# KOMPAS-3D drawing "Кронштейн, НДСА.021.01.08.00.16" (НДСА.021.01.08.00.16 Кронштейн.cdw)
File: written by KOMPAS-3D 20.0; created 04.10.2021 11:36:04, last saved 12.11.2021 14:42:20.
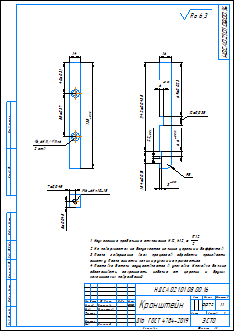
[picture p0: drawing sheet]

Sheet 1: A3, portrait

Document properties: Автор: adminzsc; Параметр неуказанной шероховатости: Ra 6,3; PLM_CDWXDTO: <item xmlns="http://appius.ru/pdm" xmlns:xs="http://www.w3.org/2001/XMLSchema" xmlns:xsi="http://www.w3.org/2001/XMLSchema-instance" xsi:type="item">  <element xmlns:d2p1="http://v8.1c.ru/8.1/data/enterprise/current-config" xsi:type="d2p1:CatalogRef.aps_Элемен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; PDM_DOCXDTO: <item xmlns="http://appius.ru/pdm" xmlns:xs="http://www.w3.org/2001/XMLSchema" xmlns:xsi="http://www.w3.org/2001/XMLSchema-instance" xsi:type="item">  <element xmlns:d2p1="http://v8.1c.ru/8.1/data/enterprise/current-config" xsi:type="d2p1:CatalogRef.aps_Элемен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; PDM_ITEMXDTO: <item xmlns="http://appius.ru/pdm" xmlns:xs="http://www.w3.org/2001/XMLSchema" xmlns:xsi="http://www.w3.org/2001/XMLSchema-instance" xsi:type="item">  <element xmlns:d2p1="http://v8.1c.ru/8.1/data/enterprise/current-config" xsi:type="d2p1:CatalogRef.aps_Элемен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; Масса: 0.07415; PDM_DRAWINGXDTO: <item xmlns="http://appius.ru/pdm" xmlns:xs="http://www.w3.org/2001/XMLSchema" xmlns:xsi="http://www.w3.org/2001/XMLSchema-instance" xsi:type="item">  <element xmlns:d2p1="http://v8.1c.ru/8.1/data/enterprise/current-config" xsi:type="d2p1:CatalogRef.aps_Элемен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

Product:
- Part/product: Кронштейн  | designation НДСА.021.01.08.00.16
    Материал: Д16  ГОСТ 4784-2019 (density 2800 kg/m3)
    Масса: 0.0741541
    additional columns: <item xmlns="http://appius.ru/pdm" xmlns:xs="http://www.w3.org/2001/XMLSchema" x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; <item xmlns="http://appius.ru/pdm" xmlns:xs="http://www.w3.org/2001/XMLSchema" x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; <item xmlns="http://appius.ru/pdm" xmlns:xs="http://www.w3.org/2001/XMLSchema" x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
    source file: НДСА.021.01.08.00.16 Кронштейн.cdw

Title block, sheet 1: Наименование: Кронштейн; designation: НДСА.021.01.08.00.16; Материал: Д16  ГОСТ 4784-2019; Масса: 0,07 г; Количество листов документа: 1; organisation: ЭСТО; Форматы листов документа: A3; stored path: C:\Users\korychko\Desktop\PLM\НДСА.021.01.08.00.16 Кронштейн.cdw; Разработал: Васильева; Проверил: Горностаев; Утвердил: Белецкий; Разработал, date: 04.10.2021

Views: Вид 1, Спереди, Проекционный вид 2, Проекционный вид 3
Referenced files in C:\Users\vasilyeva\Desktop\PM_APPIUS\: НДСА.021.01.08.00.16 Кронштейн.m3d
Referenced files in C:\Users\korychko\Desktop\PLM\: НДСА.021.01.08.00.16 Кронштейн.m3d
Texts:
  JS8
  JS10
  JS9
  JS11
  Ra 6,3
  НДСА.021.01.08.00.16 Кронштейн
Dimensions and other numbers on the sheet: 40±0,31; 55±0,37; 135; 14; 16; 69±0,023; 12±0,035; 114,2±0,0435; 15,4±0,018; 5; 6,6; 2,2; 6; 3; 7±0,045; 8±0,045; 2 отв.; 1:1; 1; 0,07 г; 04.10.2021

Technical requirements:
  Неуказанные предельные отклонения H12, h12,    IT12 2 .
  На поверхностях не допускается наличие царапин и деффектов.
  После завершения всех процессов обработки произвести
  очистку. После очистки голыми руками не прикосаться.
  Поставка детали осуществляется в упаковке. Упаковка должна
  обеспечивать сохранность изделия от царапин и других
  механических повреждений.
